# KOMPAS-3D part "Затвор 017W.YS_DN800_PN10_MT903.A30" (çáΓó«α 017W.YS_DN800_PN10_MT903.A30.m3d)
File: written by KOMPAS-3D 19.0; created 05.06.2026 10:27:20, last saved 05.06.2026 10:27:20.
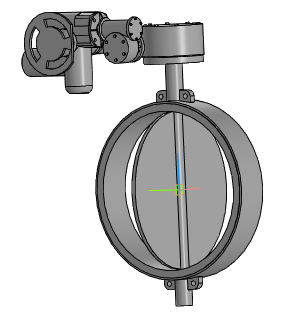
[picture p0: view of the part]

Document properties: Автор: Энергия; Полное имя файла: ..\..\..\3d для проектировщиков\x.x Тип 017W.Y(S) Затвор дисковый поворотный межфланцевый\Затвор 017W.Y(S)_DN32-DN1200_QT.A_MT903.A\Затвор 017W.YS_DN800_PN10_MT903.A30.a3d

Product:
- Part/product: Затвор 017W.YS_DN800_PN10_MT903.A30
    Масса: 623.093

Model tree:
1. Операция без истории:1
